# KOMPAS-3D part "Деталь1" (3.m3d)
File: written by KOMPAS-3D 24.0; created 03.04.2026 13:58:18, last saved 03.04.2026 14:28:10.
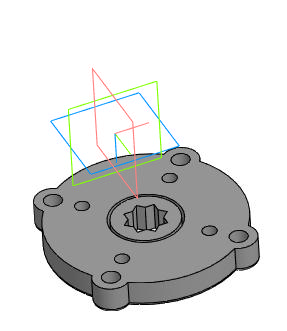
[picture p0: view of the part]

Document properties: Автор: R2D2; Полное имя файла: E:\Работа\Зайцев\Аксессуары для пневмоприводов\Ручной дублер DN.ru\MON2-450-T28-ISO Ручной дублер DN.ru\исходные материалы\3.m3d

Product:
- Body: Тело 2  | qty 1
    Масса: 7.905441
- Part/product: Деталь1
    Масса: 10.922817
    additional columns: Типовые

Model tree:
1. Операция без истории:1
2. Эскиз:1
3. Элемент выдавливания:3
     Расстояние 1 = 500
4. Элемент выдавливания:6
     Расстояние 1 = 500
